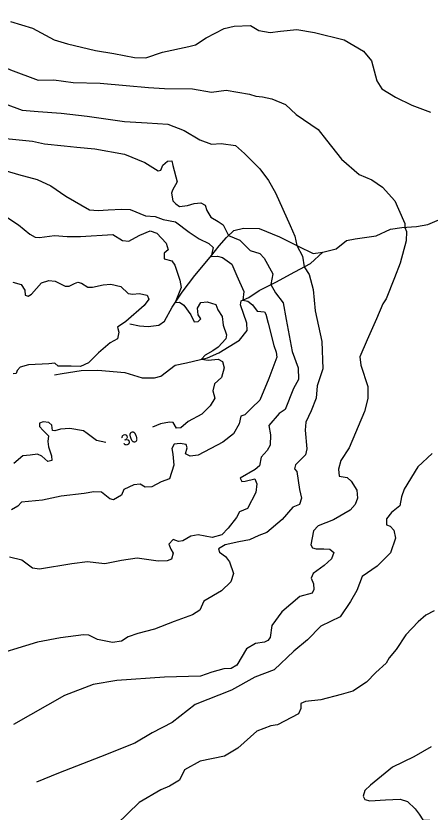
# Model space of a CAD drawing. Extents: x 646142 to 649934, y 5874075 to 5876351.
# Drawn here: x 648038.8 to 648150.2, y 5874617 to 5874831.3 of the extents above; entities that cross this region are included whole.
import ezdxf

# ---------------------------------------------------------------- set-up
doc = ezdxf.new("R2010")
doc.units = 0
for name, color, linetype in [('Niveau 1', 7, 'Continuous'), ('Niveau 2', 7, 'Continuous'), ('Niveau 4', 7, 'Continuous')]:
    doc.layers.add(name, color=color, linetype=linetype)

msp = doc.modelspace()

# ---------------------------------------------------------------- linework, layer by layer
at = {"layer": 'Niveau 1'}
for points in [[(648037.29, 5874829.83), (648043.21, 5874828.07), (648049.03, 5874824.9), (648052.65, 5874823.85), (648060.21, 5874822.03), (648065.1, 5874821.23), (648070.71, 5874820.15), (648073.76, 5874820.1), (648078.18, 5874821.6), (648085.3, 5874823.14), (648087.13, 5874823.56), (648089.99, 5874825.49), (648094.78, 5874827.97), (648097.53, 5874828.6), (648101.85, 5874828.79), (648104.1, 5874827.38), (648107.19, 5874826.86), (648109.97, 5874827.26), (648114.38, 5874827.7), (648119.14, 5874826.89), (648127.08, 5874824.87), (648132.29, 5874821.87), (648134.42, 5874819.26), (648135.88, 5874813.89), (648137.27, 5874811.68), (648140.89, 5874809.46), (648145.31, 5874807.33), (648150.3, 5874805.48)], [(648031.62, 5874780.25), (648039.45, 5874775.1), (648042.49, 5874772.61), (648043.96, 5874771.83), (648045.13, 5874771.71), (648049.15, 5874772.23), (648052.54, 5874771.99), (648056.15, 5874772), (648064.81, 5874772.53), (648067.41, 5874770.92), (648069.17, 5874770.75), (648069.94, 5874771.18), (648072.15, 5874772.33), (648074.93, 5874773.5)], [(648074.93, 5874773.5), (648076.73, 5874772.86), (648079.2, 5874770.2), (648079.73, 5874768.39), (648078.66, 5874767.47), (648078.69, 5874765.96), (648080.72, 5874765.46), (648081.53, 5874764.27), (648082.86, 5874760.21), (648083.28, 5874758.27), (648081.66, 5874754.21), (648082.81, 5874754.33), (648083.94, 5874753.51), (648085.82, 5874750.91), (648086.7, 5874749.02), (648087.85, 5874749.13), (648088.49, 5874749.78), (648087.8, 5874750.87), (648087.62, 5874752.72), (648088.51, 5874754.2), (648090.24, 5874754.38), (648092.52, 5874753.67), (648093.13, 5874752.22), (648094.23, 5874750.47), (648094.58, 5874748.06), (648095.42, 5874745.47), (648095.29, 5874744.41), (648093.18, 5874742.22), (648091.78, 5874741.15), (648089.68, 5874740.01), (648088.73, 5874738.94), (648090.5, 5874738.65), (648093.15, 5874738.92), (648094.36, 5874738.34), (648094.77, 5874736.64), (648094.09, 5874734.01), (648092.17, 5874732.31), (648091.78, 5874730.4), (648092.32, 5874728.48), (648091.01, 5874726.37), (648088.79, 5874724.17), (648085.15, 5874722.18), (648083.12, 5874720.46), (648081.97, 5874720.35), (648081.12, 5874721.89), (648080.06, 5874722.02), (648077.67, 5874721.54), (648075.49, 5874720.63)], [(648062.92, 5874716.5), (648060.46, 5874717.02), (648057.94, 5874718.98), (648056.94, 5874719.69), (648053.29, 5874720.26), (648050.74, 5874720.12), (648049.28, 5874719.62), (648048.57, 5874719.78), (648048.43, 5874721.16), (648047.66, 5874721.9), (648046.13, 5874722.1), (648045.12, 5874721.76), (648045.1, 5874720.83), (648046.13, 5874719.77), (648047.56, 5874718.28), (648047.36, 5874716.75), (648047.5, 5874715.37), (648048.32, 5874712.9), (648048.45, 5874711.63), (648047.31, 5874711.4), (648045.77, 5874712.87), (648044.56, 5874713.33), (648042.61, 5874713.14), (648040.65, 5874712.94), (648038.19, 5874710.83)], [(648150.77, 5874713.51), (648146.91, 5874709.96), (648143.28, 5874703.97), (648142.55, 5874701.9), (648142.08, 5874699.51), (648139.81, 5874697.65), (648138.45, 5874695.99), (648138.49, 5874694.35)], [(648138.49, 5874694.35), (648139.46, 5874693.98), (648140.5, 5874692.91), (648140.95, 5874690.73), (648139.58, 5874686.85), (648135.96, 5874683.2), (648131.9, 5874680.45), (648130.51, 5874676.68), (648128.82, 5874673.7), (648126.06, 5874669.56), (648120.81, 5874667.04), (648117.19, 5874663.4), (648113.52, 5874660.34), (648108.27, 5874655.36), (648103.09, 5874653.32), (648096.76, 5874649.87), (648086.97, 5874645.96), (648080.78, 5874641.12), (648075.44, 5874638.36), (648070.8, 5874635.56), (648061.57, 5874631.94), (648050.19, 5874627.52), (648044.29, 5874625.05)]]:
    msp.add_lwpolyline(points, dxfattribs=at)
at = {"layer": 'Niveau 2'}
for points in [[(647996.28, 5874834.68), (648009.51, 5874829.9), (648016.13, 5874826.82), (648019.58, 5874823.81), (648022.94, 5874822.98), (648025.39, 5874821.82), (648030.87, 5874819.67), (648037.35, 5874816.81), (648044.76, 5874814.03), (648048.97, 5874814.1), (648054.18, 5874813.45)], [(648054.18, 5874813.45), (648061.46, 5874813.25), (648061.46, 5874813.25), (648068.42, 5874812.66), (648074.44, 5874812.09), (648078.79, 5874811.82), (648086.29, 5874811.75), (648091.4, 5874810.86), (648095.33, 5874811.37), (648101.64, 5874810.27), (648103.33, 5874809.74), (648105.11, 5874809.56), (648107.62, 5874808.99), (648111.28, 5874807.48), (648114.22, 5874804.85), (648120.12, 5874800.75), (648122.39, 5874797.93), (648126.4, 5874792.83), (648131.14, 5874788.62), (648134.55, 5874787.2), (648137.43, 5874785.27), (648140.71, 5874781.61), (648141.75, 5874779.37), (648143.42, 5874775.44), (648143.42, 5874774.43), (648143.88, 5874773.3), (648143.77, 5874770.83), (648142.14, 5874764.81), (648140.66, 5874760.8), (648138.4, 5874755.19), (648137.49, 5874753.81), (648135.78, 5874749.77), (648133.29, 5874744.13), (648131.28, 5874739.6), (648131.63, 5874737.29), (648133.47, 5874731.63), (648133.44, 5874728.35), (648132.61, 5874724.87), (648128.43, 5874715.09), (648126.19, 5874711.7), (648125.61, 5874709.3), (648125.79, 5874707.45)], [(648035.88, 5874807.64), (648040.48, 5874805.99), (648044.72, 5874805.6), (648050.95, 5874805.17), (648057.93, 5874804.35), (648068, 5874802.9), (648074.1, 5874802.58), (648079.68, 5874802.2), (648084.04, 5874800.54), (648088.26, 5874798.03), (648091.42, 5874796.83), (648093.97, 5874796.97), (648097.88, 5874796.43), (648097.88, 5874796.43), (648100.3, 5874794.33), (648104.45, 5874790.18), (648106.75, 5874787.02), (648108.59, 5874783.7), (648112.6, 5874774.97), (648113.82, 5874772.06), (648114.34, 5874769.53), (648115.91, 5874766.64), (648116.3, 5874763.8), (648117.68, 5874761.71), (648118.77, 5874757.73), (648119.34, 5874751.94), (648121.08, 5874743.7), (648121.33, 5874736.36), (648119.8, 5874731.76), (648119.54, 5874728.47), (648118.24, 5874725.06), (648116.79, 5874722), (648116.65, 5874719.88), (648117.04, 5874714.78), (648116.72, 5874713.23), (648113.96, 5874710.49), (648113.71, 5874709.42), (648114.37, 5874708.67), (648115.08, 5874703.83), (648115.65, 5874701.55), (648115.12, 5874699.86), (648113.33, 5874699.1), (648110.39, 5874695.77), (648106.3, 5874692.32), (648104.16, 5874691.52), (648101.59, 5874690.33), (648098.73, 5874689.81), (648095.08, 5874688.97), (648093.32, 5874687.86), (648093.52, 5874686.95), (648095.15, 5874685.83), (648096.22, 5874684.42)], [(648035.13, 5874798.43), (648043.26, 5874797.61), (648046.48, 5874796.88), (648051.78, 5874796.36), (648055.19, 5874796), (648060.02, 5874795.55), (648067.97, 5874794.13), (648073.44, 5874791.88), (648073.44, 5874791.88), (648077.04, 5874789.67), (648077.72, 5874789.85), (648078.29, 5874791.2), (648079.58, 5874792.26), (648080.74, 5874792.38), (648080.98, 5874791.11), (648082.12, 5874786.67), (648080.94, 5874784.45), (648080.67, 5874783.61), (648080.99, 5874781.54), (648081.76, 5874780.8), (648082.77, 5874780.08), (648084.96, 5874780.3), (648086.77, 5874780.83), (648088.5, 5874781.01), (648089.73, 5874780.43), (648090.11, 5874778.95), (648091.21, 5874777.19), (648093.19, 5874775.99), (648094.57, 5874775.08), (648096.01, 5874772.27), (648099.06, 5874770.95), (648101.78, 5874768.18), (648104.42, 5874767.4), (648105.6, 5874766.11), (648107.88, 5874761.91), (648107.38, 5874759.01), (648108.64, 5874756.8), (648110.66, 5874754.08), (648111.45, 5874749.61), (648113.11, 5874741.02)], [(648036.13, 5874789.64), (648039.49, 5874788.7), (648044.51, 5874787.34), (648048.18, 5874785.6), (648052.17, 5874782.86), (648058.59, 5874779.19), (648060.94, 5874778.95), (648063.6, 5874779.11), (648067.3, 5874779.36), (648069.53, 5874779.23), (648073.65, 5874777.55), (648076.23, 5874777.34), (648078.41, 5874776.51), (648081.73, 5874775.91), (648085.38, 5874773.13), (648088.12, 5874771.31), (648090.68, 5874770.05), (648091.83, 5874769), (648091.27, 5874766.63), (648093.01, 5874766.69), (648094.32, 5874766.36), (648096.83, 5874764.51), (648098.19, 5874761.38), (648100.12, 5874757.15), (648099.79, 5874754.85), (648101.21, 5874754.53), (648102.47, 5874753.61), (648103.69, 5874751.86), (648105.68, 5874751.71), (648105.98, 5874751.04), (648106.68, 5874748.67), (648108.2, 5874742.64), (648108.84, 5874740.84), (648108.98, 5874739.46), (648106.86, 5874733.77), (648104.41, 5874727.93), (648102.29, 5874725.85), (648100.39, 5874723.92), (648099.26, 5874723.6)], [(648037.9, 5874759.64), (648040.17, 5874759.05), (648041.13, 5874757.52), (648041.27, 5874756.14), (648042.1, 5874755.87), (648042.98, 5874756.43), (648045.69, 5874759.49), (648047.6, 5874760.15), (648049.36, 5874759.97), (648052.04, 5874758.62), (648053.09, 5874758.6), (648054.52, 5874759.33), (648055.42, 5874759.65), (648056.37, 5874759.4), (648058.11, 5874758.3), (648059.38, 5874758.31), (648062.22, 5874758.94), (648064.29, 5874759.15), (648067.02, 5874758.49), (648068.95, 5874756.6), (648070.23, 5874756.49), (648071.96, 5874756.67), (648074.09, 5874756.18), (648074.55, 5874755.07), (648073.32, 5874753.43), (648068.3, 5874749.09), (648066.12, 5874747.6), (648066.49, 5874746.24), (648066.09, 5874744.46), (648064.11, 5874743.33), (648061.01, 5874740.69), (648058.26, 5874737.98), (648056.16, 5874736.95), (648053.6, 5874737.04), (648050.12, 5874737.04), (648049.22, 5874737.88), (648047.61, 5874737.72), (648042.19, 5874737.41), (648039.93, 5874736.83), (648039.09, 5874735.94), (648038.83, 5874735.1), (648038.02, 5874735.02)], [(648113.11, 5874741.02), (648114.7, 5874736.63), (648114.78, 5874733.49), (648113.51, 5874731.03), (648111.26, 5874725.43), (648109.62, 5874724.34), (648106.79, 5874721.13), (648107.27, 5874718.62), (648107.2, 5874715.81), (648106.41, 5874714.33), (648104.72, 5874712.53), (648104.36, 5874710.27), (648103.18, 5874709.22), (648099.1, 5874706.95), (648099.54, 5874706.06), (648100.46, 5874706.15), (648103.08, 5874706.76), (648103.56, 5874705.41), (648103.33, 5874703.06), (648101.07, 5874698.75), (648098.95, 5874697.83), (648098.16, 5874696.36), (648095.89, 5874693.44), (648094.2, 5874691.64), (648091.59, 5874690.91), (648087.79, 5874691.7), (648085.85, 5874691.27), (648083.64, 5874690), (648082.49, 5874689.88), (648081.04, 5874690.44), (648079.88, 5874689.15), (648080.48, 5874687.82), (648081.06, 5874686.71), (648080.63, 5874685.15), (648079.51, 5874684.69), (648077.08, 5874684.56), (648071.4, 5874685.39), (648067.16, 5874684.73), (648062.71, 5874683.81), (648060.23, 5874684.15), (648057.99, 5874684.39), (648053.85, 5874683.86), (648045.14, 5874682.4), (648043.25, 5874682.67), (648040.36, 5874684.83), (648037.01, 5874685.66)], [(648099.26, 5874723.6), (648098.88, 5874721.58), (648097.28, 5874718.86), (648094.48, 5874716.6), (648087.84, 5874713.13), (648085.67, 5874712.8), (648084.44, 5874713.49), (648084.86, 5874715.05), (648084.54, 5874715.95), (648083, 5874716.26), (648081.39, 5874716.1), (648080.69, 5874714.86), (648080.96, 5874713.37), (648081.25, 5874710.38), (648080.1, 5874706.77), (648077.85, 5874705.96), (648075.32, 5874704.54), (648073.58, 5874704.48), (648072.22, 5874705.28), (648070.49, 5874705.1), (648067.82, 5874703.9), (648067.16, 5874702.32), (648065.07, 5874701.06), (648064, 5874701.31), (648061.84, 5874703.18), (648059.74, 5874703.21), (648057.11, 5874702.83), (648050.9, 5874702.09), (648045.89, 5874701), (648040.24, 5874700.43), (648039.3, 5874699.41), (648037.54, 5874698.41)], [(648125.79, 5874707.45), (648127.93, 5874707.08), (648128.96, 5874706.13), (648130.48, 5874703.71), (648130.7, 5874701.51), (648130.05, 5874699.8), (648128.68, 5874698.26), (648124.26, 5874695.71), (648120.09, 5874694.12), (648118.83, 5874692.71), (648118.14, 5874689.01), (648118.58, 5874688.12), (648119.54, 5874687.87), (648121.64, 5874687.85), (648123.28, 5874687.78), (648124.3, 5874686.94), (648123.65, 5874685.24), (648121.73, 5874683.41), (648118.79, 5874681.24), (648118.2, 5874680.02), (648118.83, 5874678.44), (648118.98, 5874676.94), (648118.49, 5874675.95), (648115.19, 5874675.04), (648110.34, 5874670.92), (648107.66, 5874667.26), (648107.16, 5874664.06), (648106.54, 5874663.18), (648105.65, 5874662.74), (648103.23, 5874662.38), (648100.8, 5874660.96), (648098.2, 5874656.61), (648096.66, 5874655.64), (648094.68, 5874655.55), (648091.5, 5874654.65), (648088.44, 5874653.64), (648078.77, 5874653.37), (648065.9, 5874652.43), (648059.58, 5874651.33), (648051.81, 5874648.44), (648038.1, 5874640.63)], [(648096.22, 5874684.42), (648097.35, 5874681.26), (648096.64, 5874678.97), (648094.08, 5874676.61), (648089.34, 5874673.8), (648088.3, 5874671.36), (648086.32, 5874670.11), (648081.36, 5874668.33), (648076.08, 5874666.28), (648071.53, 5874665.12), (648068.94, 5874664.16), (648067.19, 5874663.05), (648064.77, 5874662.69), (648060.73, 5874663.45), (648058.4, 5874664.62), (648056.99, 5874664.71), (648050.76, 5874663.97), (648044.58, 5874662.77), (648030.43, 5874658.43), (648011.59, 5874651.98), (648003.29, 5874649.25)], [(648151.31, 5874671.17), (648149.08, 5874670), (648147.02, 5874668.27), (648143.73, 5874664.78), (648141.08, 5874660.76), (648139.18, 5874658.57), (648138.39, 5874657.09), (648135.59, 5874654.58), (648133.15, 5874651.99), (648129.4, 5874649.62), (648126.33, 5874648.72), (648120.85, 5874647.23), (648116.67, 5874646.81), (648115.44, 5874646.22), (648115.45, 5874644.93), (648114.77, 5874643.46), (648109.2, 5874640.55), (648107.36, 5874640.25), (648103.63, 5874638.82), (648098.46, 5874634.2), (648094.92, 5874632.08), (648088.38, 5874630.72), (648084.16, 5874628.42), (648082.79, 5874625.59), (648080.14, 5874624.04), (648077.78, 5874622.98), (648071.91, 5874619.58), (648059.83, 5874607.82)], [(648150.52, 5874634.61), (648145.86, 5874631.91), (648140.15, 5874629.11), (648134.17, 5874624.28), (648132.67, 5874622.84), (648132.24, 5874621.27), (648132.68, 5874620.38), (648134, 5874620.04), (648138.2, 5874620.34), (648142.17, 5874620.51), (648144.11, 5874619.88), (648146.18, 5874617.86), (648147.26, 5874616.44), (648148.23, 5874614.9), (648150.11, 5874614.85), (648151.66, 5874614.66)]]:
    msp.add_lwpolyline(points, dxfattribs=at)
at = {"layer": 'Niveau 4'}
for points in [[(648069.39, 5874748.5), (648071.99, 5874747.95), (648074.34, 5874747.72), (648077.2, 5874748.13), (648078.72, 5874749.21), (648080.79, 5874752.91), (648083.52, 5874757.02), (648086.92, 5874761.44), (648091.5, 5874766.91), (648093.46, 5874769.44), (648095.45, 5874771.74), (648097.37, 5874773.57), (648099.99, 5874774.18), (648104.2, 5874774.13), (648109.67, 5874771.88), (648114.7, 5874769.34), (648118.75, 5874767.41), (648121.39, 5874767.79), (648124.93, 5874768.62), (648127.75, 5874770.89), (648130.04, 5874771.35), (648135.69, 5874772.15), (648139.6, 5874773.95), (648142.6, 5874774.37), (648146.55, 5874774.65), (648149.65, 5874775.2), (648155.05, 5874777.5)], [(648049.12, 5874734.73), (648051.18, 5874735.05), (648056.32, 5874735.92), (648060.84, 5874736.02), (648068.1, 5874735.36), (648072.77, 5874733.96), (648076.02, 5874733.94), (648077.72, 5874734.35), (648081.61, 5874737.3), (648084.68, 5874737.95), (648090.36, 5874739.34), (648093.36, 5874740.69), (648098.96, 5874744.04), (648101.02, 5874746.69), (648100.94, 5874748.67), (648099.18, 5874753.61), (648099.42, 5874754.69), (648101.42, 5874755.59), (648104.27, 5874757.39), (648108.71, 5874759.7), (648113.8, 5874762.43), (648118.01, 5874764.73), (648121.39, 5874767.79)]]:
    msp.add_lwpolyline(points, dxfattribs=at)

# ---------------------------------------------------------------- texts
at = {"layer": 'Niveau 1'}
msp.add_text('30', height=3, rotation=19.6082, dxfattribs=at).set_placement((648067.75, 5874715.46))

doc.saveas('drawing.dxf')
